Omron CX-Programmer project NewProject (CX-Programmer 9.21)

# PLC NewPLC1: CJ1M CPU11
I/O table (CPU CJ1M-CPU11): rack 0 slot 0 CJ1W-ID211; rack 0 slot 1 CJ1W-OC211; rack 0 slot 2 CJ1W-DRM21

## Global symbols (name address type ; comment)
AttributeID D1004 UINT_BCD  ; Attribute ID (Hex)
ClassID D1002 UINT_BCD  ; Class ID (Hex)
CommandCode D1000 UINT_BCD  ; Command Code
DataReceived D2004 UINT_BCD  ; Data Received
DestinationNetworkAddress D2 UDINT_BCD  ; Destination Network Address (Hex)
DestinationNodeAddress_DestinationUnitAddress D3 UINT_BCD  ; $?St$Bk?_#[112] / MSB - Destination Node Address (Hex) / LSB - Destination Unit Address (Hex)$?St$Bk?_#[112]
ExecutionBit W0.00 BOOL  ; Execution Bit
InstanceID D1003 UINT_BCD  ; Instance ID (Hex)
NodeAddressServiceCode D1001 UINT_BCD  ; $?St$Bk?_#[113] / Node Address / Service Code / MSB - Node Address (Hex) / LSB - Service Code (Hex)$?St$Bk?_#[113]
NumberOfCommandBytes D0 UINT_BCD  ; Number Of Command Bytes (Hex)
NumberOfResponseBytes D1 UINT_BCD  ; Number Of Response Bytes (Hex)
PortEnabledFlag A202.00 BOOL  ; Communications Port #1 Enabled Flag
Response D2003 UINT_BCD  ; $?St$Bk?_#[115] / MSB - Response Source Node Address (Hex) / LSB - Normal Completion (Hex) / should be 8E$?St$Bk?_#[115]
ResponseCommandCode D2000 UINT_BCD  ; Response Command Code
ResponseMonitoringTime D5 UINT_BCD  ; Response Monitoring Time
Response_CommunicationsPort0_NoRetries D4 UINT_BCD  ; Response, Communications Port 0, No Retries (Hex)

## Program NewProgram1 (cyclic task 0)
; The vendor code is read from a Slave (OMRON vendor code: 002F Hex) using the EXPLICIT MESSAGE SEND command, 2801. / The command data is written starting at D1000, and the response data is stored starting at D2000. / When execution of CMND(490) has been completed, the completion code is stored in D00006 and the instruction is executed again. / *** NOTE - The actual data will be found in D2004. *** / This example assumes an Omron Corporation manufactured DeviceNet slave (value in D2004 will be #2F00). / The Vendor ID for all DeviceNet manufacturer's can be found at http://www.odva.org/

### Section Section1

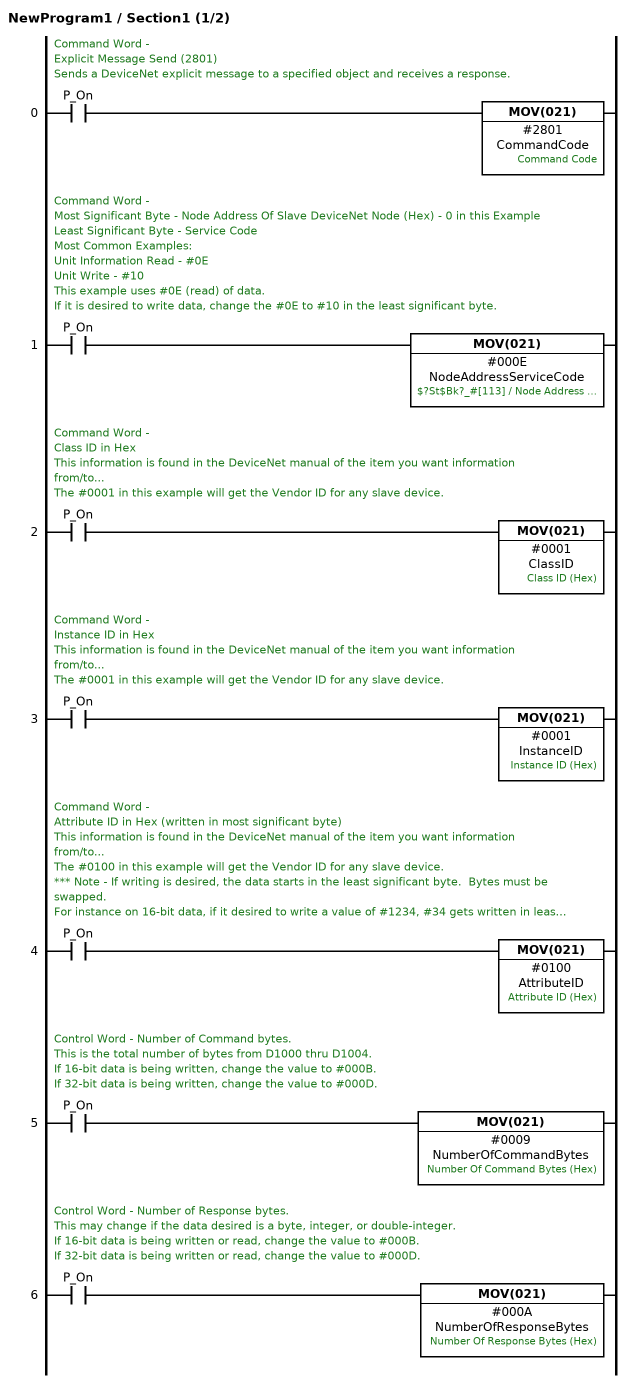
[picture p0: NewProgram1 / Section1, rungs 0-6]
; rung 0: Command Word - / Explicit Message Send (2801) / Sends a DeviceNet explicit message to a specified object and receives a response.
LD P_On
MOV(021) #2801 CommandCode  ; Command Code
; rung 1: Command Word - / Most Significant Byte - Node Address Of Slave DeviceNet Node (Hex) - 0 in this Example / Least Significant Byte - Service Code / Most Common Examples: / Unit Information Read - #0E / Unit Write - #10 / This example uses #0E (read) of data. / If it is desired to write data, change the #0E to #10 in the least significant byte.
LD P_On
MOV(021) #000E NodeAddressServiceCode  ; $?St$Bk?_#[113] / Node Address / Service Code / MSB - Node Address (Hex) / LSB - Service Code (Hex)$?St$Bk?_#[113]
; rung 2: Command Word - / Class ID in Hex / This information is found in the DeviceNet manual of the item you want information from/to... / The #0001 in this example will get the Vendor ID for any slave device.
LD P_On
MOV(021) #0001 ClassID  ; Class ID (Hex)
; rung 3: Command Word - / Instance ID in Hex / This information is found in the DeviceNet manual of the item you want information from/to... / The #0001 in this example will get the Vendor ID for any slave device.
LD P_On
MOV(021) #0001 InstanceID  ; Instance ID (Hex)
; rung 4: Command Word - / Attribute ID in Hex (written in most significant byte) / This information is found in the DeviceNet manual of the item you want information from/to... / The #0100 in this example will get the Vendor ID for any slave device. / *** Note - If writing is desired, the data starts in the least significant byte.  Bytes must be swapped. / For instance on 16-bit data, if it desired to write a value of #1234, #34 gets written in least significant byte of D1004 & #12 gets written in most significant byte of D1005. / For instance on 32-bit data, if it desired to write a value of #12345678, #78 gets written in least significant byte of D1004, #56 gets written in most significant byte of D1005, / #34 gets written in least significant byte of D1005, and #12 gets written in most significant byte of D1006.
LD P_On
MOV(021) #0100 AttributeID  ; Attribute ID (Hex)
; rung 5: Control Word - Number of Command bytes. / This is the total number of bytes from D1000 thru D1004. / If 16-bit data is being written, change the value to #000B. / If 32-bit data is being written, change the value to #000D.
LD P_On
MOV(021) #0009 NumberOfCommandBytes  ; Number Of Command Bytes (Hex)
; rung 6: Control Word - Number of Response bytes. / This may change if the data desired is a byte, integer, or double-integer. / If 16-bit data is being written or read, change the value to #000B. / If 32-bit data is being written or read, change the value to #000D.
LD P_On
MOV(021) #000A NumberOfResponseBytes  ; Number Of Response Bytes (Hex)

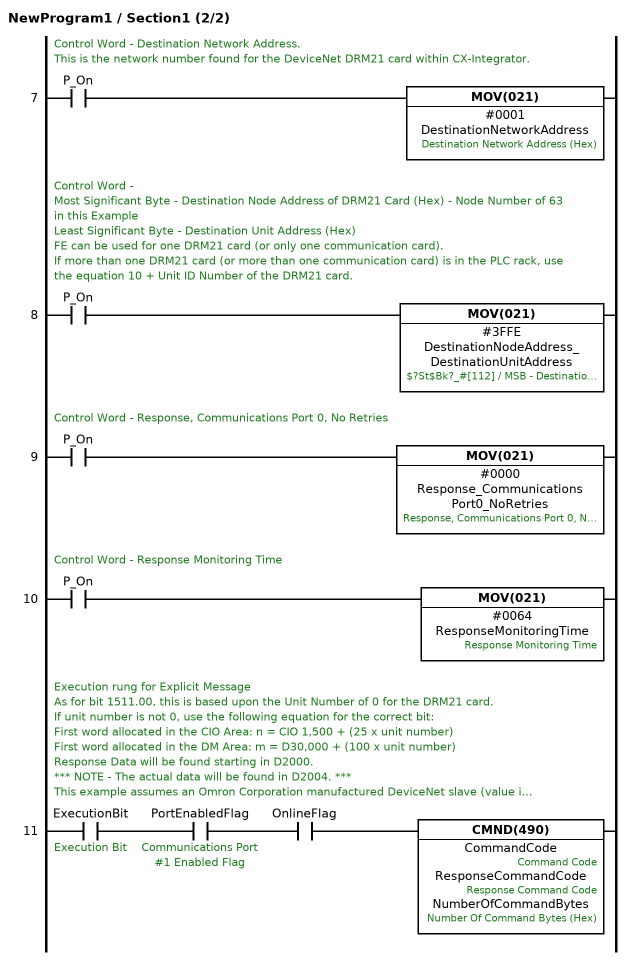
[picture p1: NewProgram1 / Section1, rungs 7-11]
; rung 7: Control Word - Destination Network Address. / This is the network number found for the DeviceNet DRM21 card within CX-Integrator.
LD P_On
MOV(021) #0001 DestinationNetworkAddress  ; Destination Network Address (Hex)
; rung 8: Control Word - / Most Significant Byte - Destination Node Address of DRM21 Card (Hex) - Node Number of 63 in this Example / Least Significant Byte - Destination Unit Address (Hex) / FE can be used for one DRM21 card (or only one communication card). / If more than one DRM21 card (or more than one communication card) is in the PLC rack, use the equation 10 + Unit ID Number of the DRM21 card.
LD P_On
MOV(021) #3FFE DestinationNodeAddress_DestinationUnitAddress  ; $?St$Bk?_#[112] / MSB - Destination Node Address (Hex) / LSB - Destination Unit Address (Hex)$?St$Bk?_#[112]
; rung 9: Control Word - Response, Communications Port 0, No Retries
LD P_On
MOV(021) #0000 Response_CommunicationsPort0_NoRetries  ; Response, Communications Port 0, No Retries (Hex)
; rung 10: Control Word - Response Monitoring Time
LD P_On
MOV(021) #0064 ResponseMonitoringTime  ; Response Monitoring Time
; rung 11: Execution rung for Explicit Message / As for bit 1511.00, this is based upon the Unit Number of 0 for the DRM21 card. / If unit number is not 0, use the following equation for the correct bit: / First word allocated in the CIO Area: n = CIO 1,500 + (25 x unit number) / First word allocated in the DM Area: m = D30,000 + (100 x unit number) / Response Data will be found starting in D2000. / *** NOTE - The actual data will be found in D2004. *** / This example assumes an Omron Corporation manufactured DeviceNet slave (value in D2004 will be #2F00). / The Vendor ID for all DeviceNet manufacturer's can be found at http://www.odva.org/ / Bytes are swapped within the response data. / For instance on 16-bit data, if it desired to read a known value of #1234, #34 gets written in most significant byte of D2004 & #12 gets written in least significant byte of D2004. / For instance on 32-bit data, if it desired to read a known value of #12345678, #78 gets written in most significant byte of D2004, #56 gets written in least significant byte of D2004, / #34 gets written in most significant byte of D2005, and #12 gets written in least significant byte of D2005.
LD ExecutionBit  ; Execution Bit
AND PortEnabledFlag  ; Communications Port #1 Enabled Flag
AND OnlineFlag
CMND(490) CommandCode ResponseCommandCode NumberOfCommandBytes  ; Command Code, Response Command Code, Number Of Command Bytes (Hex)

### Section END
; rung 0
END(001)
